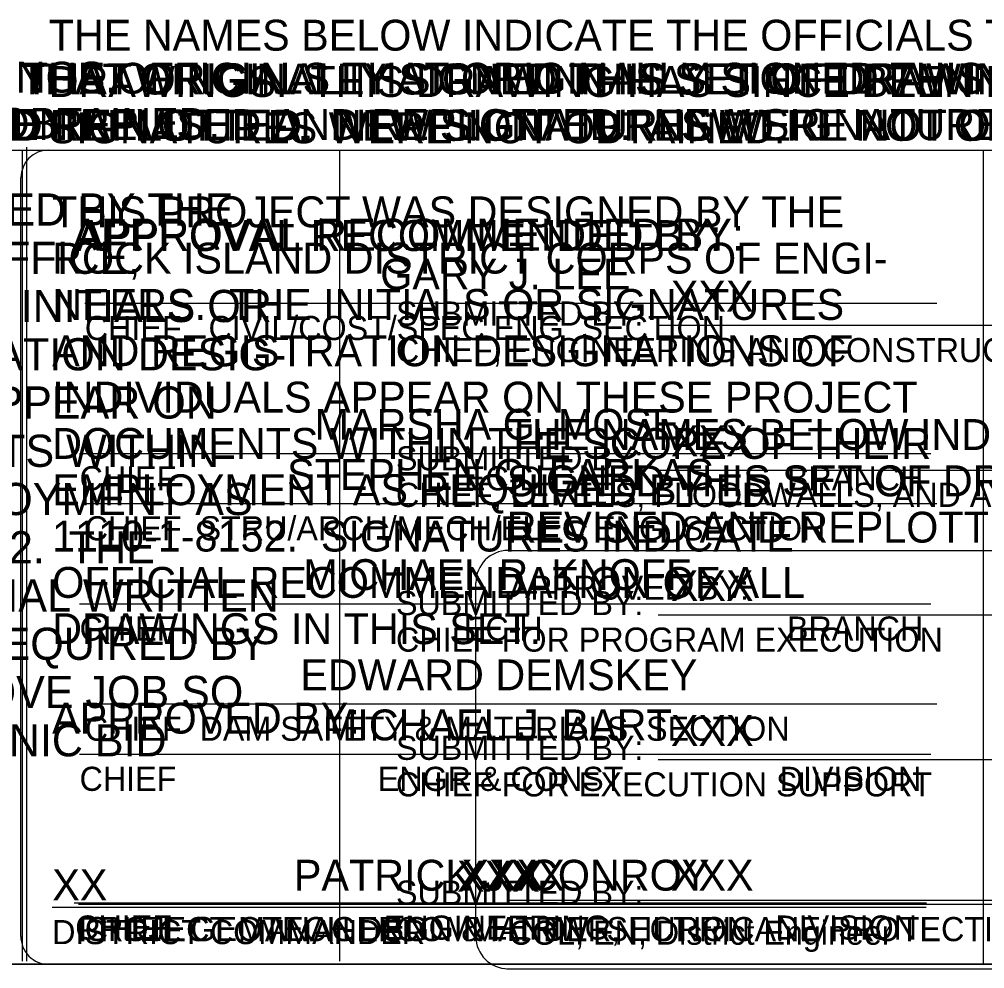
# Model space of a CAD drawing. Extents: x 0 to 2.77, y 0 to 1.73.
# Drawn here: x 1.9672 to 2.2797, y 0.0679 to 0.3753 of the extents above; entities that cross this region are included whole.
import ezdxf

# ---------------------------------------------------------------- set-up
doc = ezdxf.new("R2010")
doc.units = 0
for name, color, linetype in [('G-ANNO-TEXT-HPOA', 7, 'Continuous'), ('G-ANNO-TEXT-HPOS', 7, 'Continuous'), ('G-ANNO-TEXT-MVKA', 7, 'Continuous'), ('G-ANNO-TEXT-MVKS', 7, 'Continuous'), ('G-ANNO-TEXT-MVNA', 7, 'Continuous'), ('G-ANNO-TEXT-MVNS', 7, 'Continuous'), ('G-ANNO-TEXT-MVPA', 7, 'Continuous'), ('G-ANNO-TEXT-MVPS', 7, 'Continuous'), ('G-ANNO-TEXT-MVRA', 7, 'Continuous'), ('G-ANNO-TEXT-MVRS', 7, 'Continuous'), ('G-ANNO-TEXT-MVSA', 7, 'Continuous'), ('G-ANNO-TEXT-MVSS', 7, 'Continuous')]:
    doc.layers.add(name, color=color, linetype=linetype)

msp = doc.modelspace()

# ---------------------------------------------------------------- linework, layer by layer
at = {"layer": 'G-ANNO-TEXT-HPOS'}
for p, q in [((1.76837, 0.33296), (2.58269, 0.33296)), ((1.76837, 0.33296), (2.58269, 0.33296)), ((2.46038, 0.27613), (2.17403, 0.27613)), ((2.46038, 0.27613), (2.17403, 0.27613)), ((2.46038, 0.22926), (2.17403, 0.22926)), ((2.46038, 0.22926), (2.17403, 0.22926)), ((2.46038, 0.18238), (2.17403, 0.18238)), ((2.46038, 0.18238), (2.17403, 0.18238)), ((2.46038, 0.13551), (2.17403, 0.13551)), ((2.46038, 0.13551), (2.17403, 0.13551)), ((2.46038, 0.08863), (2.17403, 0.08863)), ((2.46038, 0.08863), (2.17403, 0.08863)), ((2.58269, 0.0693), (1.76837, 0.06929)), ((2.58269, 0.0693), (1.76837, 0.06929))]:
    msp.add_line(p, q, dxfattribs=at)
msp.add_lwpolyline([(2.07086, 0.33296), (2.07086, 0.0703)], dxfattribs=at)
msp.add_lwpolyline([(2.07086, 0.33296), (2.07086, 0.0703)], dxfattribs=at)
at = {"layer": 'G-ANNO-TEXT-MVKS'}
for p, q in [((2.12539, 0.20331), (2.58127, 0.20331)), ((2.34489, 0.09001), (2.12572, 0.09001))]:
    msp.add_line(p, q, dxfattribs=at)
for points in [[(2.11497, 0.0783), (2.11497, 0.19289)], [(2.12497, 0.06789), (2.58127, 0.06789)]]:
    msp.add_lwpolyline(points, dxfattribs=at)
for centre, start, end in [((2.12539, 0.19289), 90, 180), ((2.12539, 0.0783), 180, 270)]:
    msp.add_arc(centre, 0.01042, start, end, dxfattribs=at)
at = {"layer": 'G-ANNO-TEXT-MVNS'}
for p, q in [((1.6642, 0.33297), (2.58269, 0.33297)), ((2.2608, 0.08914), (1.98496, 0.08914)), ((2.58269, 0.0693), (1.6642, 0.06931))]:
    msp.add_line(p, q, dxfattribs=at)
msp.add_lwpolyline([(2.27919, 0.33297), (2.27919, 0.0703)], dxfattribs=at)
at = {"layer": 'G-ANNO-TEXT-MVPS'}
for p, q in [((1.66561, 0.33297), (2.58269, 0.33297)), ((2.26221, 0.23464), (1.9867, 0.23464)), ((2.26221, 0.18597), (1.9867, 0.18597)), ((2.26221, 0.1373), (1.9867, 0.1373)), ((2.26221, 0.08864), (1.98636, 0.08864)), ((2.58269, 0.0693), (1.66561, 0.0693))]:
    msp.add_line(p, q, dxfattribs=at)
msp.add_lwpolyline([(1.9681, 0.33297), (1.9681, 0.0703)], dxfattribs=at)
at = {"layer": 'G-ANNO-TEXT-MVRS'}
for p, q in [((1.97668, 0.33298), (2.58268, 0.33299)), ((1.96768, 0.27433), (1.96768, 0.32398)), ((1.96768, 0.07831), (1.96768, 0.27433)), ((2.26069, 0.08767), (1.97784, 0.08767)), ((2.58268, 0.06932), (1.97668, 0.06931))]:
    msp.add_line(p, q, dxfattribs=at)
msp.add_lwpolyline([(2.27918, 0.332), (2.27918, 0.06933)], dxfattribs=at)
for centre, start, end in [((1.97668, 0.32398), 90.0013, 179.9964), ((1.97668, 0.07831), 180.001, 270.0013)]:
    msp.add_arc(centre, 0.009, start, end, dxfattribs=at)
at = {"layer": 'G-ANNO-TEXT-MVSS'}
for p, q in [((1.35453, 0.33296), (2.58269, 0.33296)), ((2.26423, 0.2833), (1.98838, 0.2833)), ((2.26422, 0.21841), (1.98838, 0.21841)), ((2.26423, 0.15352), (1.98838, 0.15352)), ((2.26423, 0.08863), (1.98837, 0.08863)), ((2.58269, 0.0693), (1.35453, 0.06929))]:
    msp.add_line(p, q, dxfattribs=at)
msp.add_lwpolyline([(1.96953, 0.33396), (1.96953, 0.0703)], dxfattribs=at)

# ---------------------------------------------------------------- texts
at = {"layer": 'G-ANNO-TEXT-HPOA'}
for s, p in [('THE NAMES BELOW INDICATE THE OFFICIALS THAT ORIGINALLY SIGNED THIS SET OF DRAWINGS.', (1.76838, 0.35123)), ('THIS DRAWING HAS SINCE BEEN REVISED AND REPLOTTED.  NEW SIGNATURES WERE NOT OBTAINED.', (1.76838, 0.33623)), ('XXX', (2.17811, 0.28066)), ('XXX', (2.17811, 0.23379)), ('XXX', (2.17811, 0.18691)), ('XXX', (2.17811, 0.14004)), ('XXX', (2.17811, 0.09316))]:
    msp.add_text(s, height=0.01, rotation=360, dxfattribs=at).set_placement(p)
at = {"layer": 'G-ANNO-TEXT-HPOS'}
for s, height, p in [('THIS PROJECT WAS DESIGNED BY THE ', 0.0104167, (1.76952, 0.30853)), ('THIS PROJECT WAS DESIGNED BY THE ', 0.0104167, (1.76952, 0.30853)), ('HURRICANE PROTECTION OFFICE, ', 0.0104167, (1.76952, 0.2929)), ('HURRICANE PROTECTION OFFICE, ', 0.0104167, (1.76952, 0.2929)), ('CORPS OF ENGINEERS. THE INITIALS OR ', 0.0104167, (1.76952, 0.27728)), ('CORPS OF ENGINEERS. THE INITIALS OR ', 0.0104167, (1.76952, 0.27728)), ('SUBMITTED BY:', 0.0078125, (2.08912, 0.27613)), ('SUBMITTED BY:', 0.0078125, (2.08912, 0.27613)), ('SIGNATURES AND REGISTRATION DESIG-', 0.0104167, (1.76952, 0.26165)), ('SIGNATURES AND REGISTRATION DESIG-', 0.0104167, (1.76952, 0.26165)), ('CHIEF, ENGINEERING AND CONSTRUCTION', 0.0078125, (2.08911, 0.2643)), ('CHIEF, ENGINEERING AND CONSTRUCTION', 0.0078125, (2.08911, 0.2643)), ('NATIONS OF INDIVIDUALS APPEAR ON ', 0.0104167, (1.76952, 0.24603)), ('NATIONS OF INDIVIDUALS APPEAR ON ', 0.0104167, (1.76952, 0.24603)), ('THESE PROJECT DOCUMENTS WITHIN ', 0.0104167, (1.76952, 0.2304)), ('THESE PROJECT DOCUMENTS WITHIN ', 0.0104167, (1.76952, 0.2304)), ('SUBMITTED BY:', 0.0078125, (2.08912, 0.22926)), ('SUBMITTED BY:', 0.0078125, (2.08912, 0.22926)), ('THE SCOPE OF THEIR EMPLOYMENT AS ', 0.0104167, (1.76952, 0.21478)), ('THE SCOPE OF THEIR EMPLOYMENT AS ', 0.0104167, (1.76952, 0.21478)), ('CHIEF, LEVEES, FLOODWALLS, AND ARMORING', 0.0078125, (2.08911, 0.21742)), ('CHIEF, LEVEES, FLOODWALLS, AND ARMORING', 0.0078125, (2.08911, 0.21742)), ('REQUIRED BY ER 1110-1-8152.  THE ', 0.0104167, (1.76952, 0.19915)), ('REQUIRED BY ER 1110-1-8152.  THE ', 0.0104167, (1.76952, 0.19915)), ('FOLLOWING ARE THE OFFICIAL WRITTEN ', 0.0104167, (1.76952, 0.18353)), ('FOLLOWING ARE THE OFFICIAL WRITTEN ', 0.0104167, (1.76952, 0.18353)), ('SUBMITTED BY:', 0.0078125, (2.08912, 0.18238)), ('SUBMITTED BY:', 0.0078125, (2.08912, 0.18238)), ('RECORD OF SIGNATURES REQUIRED BY', 0.0104167, (1.76952, 0.1679)), ('RECORD OF SIGNATURES REQUIRED BY', 0.0104167, (1.76952, 0.1679)), ('CHIEF FOR PROGRAM EXECUTION', 0.0078125, (2.08911, 0.17055)), ('CHIEF FOR PROGRAM EXECUTION', 0.0078125, (2.08911, 0.17055)), ('ER1110-1-8152 FOR THE ABOVE JOB SO ', 0.0104167, (1.76952, 0.15228)), ('ER1110-1-8152 FOR THE ABOVE JOB SO ', 0.0104167, (1.76952, 0.15228)), ('AS TO FACILITATE ELECTRONIC BID ', 0.0104167, (1.76952, 0.13665)), ('AS TO FACILITATE ELECTRONIC BID ', 0.0104167, (1.76952, 0.13665)), ('SUBMITTED BY:', 0.0078125, (2.08912, 0.13551)), ('SUBMITTED BY:', 0.0078125, (2.08912, 0.13551)), ('CHIEF FOR EXECUTION SUPPORT', 0.0078125, (2.08911, 0.12367)), ('CHIEF FOR EXECUTION SUPPORT', 0.0078125, (2.08911, 0.12367)), ('SUBMITTED BY:', 0.0078125, (2.08912, 0.08863)), ('SUBMITTED BY:', 0.0078125, (2.08912, 0.08863)), ('COMMANDER, HURRICANE PROTECTION OFFICE', 0.0078125, (2.08911, 0.0768)), ('COMMANDER, HURRICANE PROTECTION OFFICE', 0.0078125, (2.08911, 0.0768))]:
    msp.add_text(s, height=height, rotation=360, dxfattribs=at).set_placement(p)
at = {"layer": 'G-ANNO-TEXT-MVKA'}
for s, p in [('THE NAMES BELOW INDICATE THE OFFICIALS THAT ORIGINALLY ', (2.12498, 0.23587)), ('THE NAMES BELOW INDICATE THE OFFICIALS THAT ORIGINALLY ', (2.12498, 0.23587)), ('SIGNED THIS SET OF DRAWINGS.  THIS DRAWING HAS SINCE BEEN ', (2.12498, 0.22087)), ('SIGNED THIS SET OF DRAWINGS.  THIS DRAWING HAS SINCE BEEN ', (2.12498, 0.22087)), ('REVISED AND REPLOTTED.  NEW SIGNATURES WERE NOT OBTAINED.', (2.12498, 0.20587)), ('REVISED AND REPLOTTED.  NEW SIGNATURES WERE NOT OBTAINED.', (2.12498, 0.20587)), ('XX', (2.12591, 0.09314)), ('XX', (2.12591, 0.09314))]:
    msp.add_text(s, height=0.01, rotation=360, dxfattribs=at).set_placement(p)
at = {"layer": 'G-ANNO-TEXT-MVKS'}
for s, p in [('APPROVED BY:', (2.12563, 0.18735)), ('COL, EN, District Engineer', (2.12563, 0.07564))]:
    msp.add_text(s, height=0.0078125, rotation=360, dxfattribs=at).set_placement(p)
at = {"layer": 'G-ANNO-TEXT-MVNA'}
for s, p in [('THE NAMES BELOW INDICATE THE OFFICIALS THAT ORIGINALLY SIGNED THIS SET OF DRAWINGS.', (1.6642, 0.35098)), ('THIS DRAWING HAS SINCE BEEN REVISED AND REPLOTTED.  NEW SIGNATURES WERE NOT OBTAINED.', (1.6642, 0.33598)), ('XXX', (2.1089, 0.09282))]:
    msp.add_text(s, height=0.01, rotation=360, dxfattribs=at).set_placement(p)
at = {"layer": 'G-ANNO-TEXT-MVNS'}
for s, height, p in [('APPROVAL RECOMMENDED BY:', 0.0104167, (1.98428, 0.30037)), ('CHIEF', 0.007812, (1.98528, 0.07731)), ('ENGINEERING', 0.0078125, (2.08515, 0.0773)), ('DIVISION', 0.007812, (2.21192, 0.07731))]:
    msp.add_text(s, height=height, rotation=360, dxfattribs=at).set_placement(p)
at = {"layer": 'G-ANNO-TEXT-MVPA'}
for s, p in [('THE NAMES BELOW INDICATE THE OFFICIALS THAT ORIGINALLY SIGNED THIS SET OF DRAWINGS.', (1.66563, 0.35104)), ('THIS DRAWING HAS SINCE BEEN REVISED AND REPLOTTED.  NEW SIGNATURES WERE NOT OBTAINED.', (1.66563, 0.33604)), ('MARSHA G. MOSE', (2.06275, 0.23917)), ('MICHAEL R. KNOFF', (2.05913, 0.1905)), ('MICHAEL J. BART', (2.06546, 0.14183)), ('XXX', (2.11033, 0.09317))]:
    msp.add_text(s, height=0.01, rotation=360, dxfattribs=at).set_placement(p)
at = {"layer": 'G-ANNO-TEXT-MVPS'}
for s, height, p in [('APPROVAL RECOMMENDED BY:', 0.01, (1.98569, 0.30028)), ('CHIEF', 0.007812, (1.98669, 0.2228)), ('EC-D', 0.007812, (2.11111, 0.22279)), ('BRANCH', 0.007812, (2.21569, 0.2228)), ('CHIEF', 0.007812, (1.98669, 0.17414)), ('EC-H', 0.007812, (2.11108, 0.17412)), ('BRANCH', 0.007812, (2.21569, 0.17414)), ('CHIEF', 0.007812, (1.98669, 0.12547)), ('ENGR & CONST', 0.0078125, (2.08322, 0.12546)), ('DIVISION', 0.007812, (2.21333, 0.12547)), ('PROJECT MANAGER', 0.0078125, (1.98636, 0.0768))]:
    msp.add_text(s, height=height, rotation=360, dxfattribs=at).set_placement(p)
at = {"layer": 'G-ANNO-TEXT-MVRA'}
for s, p in [('THE NAMES BELOW INDICATE THE OFFICIALS THAT ORIGINALLY SIGNED THIS SET OF ', (1.9767, 0.36518)), ('DRAWINGS.  THIS DRAWING HAS SINCE BEEN REVISED AND REPLOTTED.  NEW ', (1.9767, 0.35018)), ('SIGNATURES WERE NOT OBTAINED.', (1.9767, 0.33518)), ('XX', (1.97786, 0.09001))]:
    msp.add_text(s, height=0.01, rotation=360, dxfattribs=at).set_placement(p)
at = {"layer": 'G-ANNO-TEXT-MVRS'}
for s, height, p in [('THIS PROJECT WAS DESIGNED BY THE ', 0.01, (1.97783, 0.30798)), ('ROCK ISLAND DISTRICT CORPS OF ENGI-', 0.01, (1.97783, 0.29298)), ('NEERS.  THE INITIALS OR SIGNATURES ', 0.01, (1.97783, 0.27798)), ('AND REGISTRATION DESIGNATIONS OF ', 0.01, (1.97783, 0.26298)), ('INDIVIDUALS APPEAR ON THESE PROJECT ', 0.01, (1.97783, 0.24798)), ('DOCUMENTS WITHIN THE SCOPE OF THEIR ', 0.01, (1.97783, 0.23298)), ('EMPLOYMENT AS REQUIRED BY ER ', 0.01, (1.97783, 0.21798)), ('1110-1-8152.  SIGNATURES INDICATE ', 0.01, (1.97783, 0.20298)), ('OFFICIAL RECOMMENDATION OF ALL ', 0.01, (1.97783, 0.18798)), ('DRAWINGS IN THIS SET.', 0.01, (1.97783, 0.17298)), ('APPROVED BY:', 0.01, (1.97782, 0.14402)), ('DISTRICT COMMANDER', 0.0078125, (1.97782, 0.07583))]:
    msp.add_text(s, height=height, rotation=360, dxfattribs=at).set_placement(p)
at = {"layer": 'G-ANNO-TEXT-MVSA'}
for s, p in [('THE NAMES BELOW INDICATE THE OFFICIALS THAT ORIGINALLY SIGNED THIS SET OF DRAWINGS.  ', (1.35455, 0.3516)), ('THIS DRAWING HAS SINCE BEEN REVISED AND REPLOTTED.  NEW SIGNATURES WERE NOT OBTAINED.', (1.35455, 0.3366)), ('GARY J. LEE', (2.08402, 0.28783)), ('STEPHEN G. FARKAS', (2.05386, 0.22294)), ('EDWARD DEMSKEY', (2.05814, 0.15805)), ('PATRICK J. CONROY', (2.05607, 0.09316))]:
    msp.add_text(s, height=0.01, rotation=360, dxfattribs=at).set_placement(p)
at = {"layer": 'G-ANNO-TEXT-MVSS'}
for s, p in [('CHIEF   CIVIL/COST/SPEC ENG  SECTION', (1.98838, 0.27146)), ('CHIEF  STRU/ARCH/MECH/ELEC ENG  SECTION', (1.98839, 0.20659)), ('CHIEF  DAM SAFETY & MATERIALS  SECTION', (1.98839, 0.1417)), ('CHIEF GEOTECH DSGN & HTRW  SECTION', (1.98838, 0.07681))]:
    msp.add_text(s, height=0.0078125, rotation=360, dxfattribs=at).set_placement(p)

doc.saveas('drawing.dxf')
